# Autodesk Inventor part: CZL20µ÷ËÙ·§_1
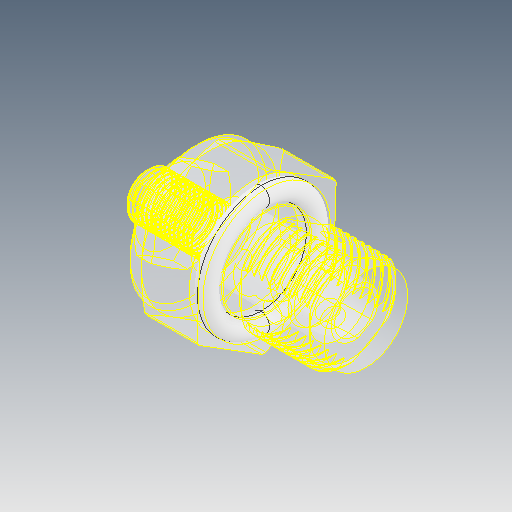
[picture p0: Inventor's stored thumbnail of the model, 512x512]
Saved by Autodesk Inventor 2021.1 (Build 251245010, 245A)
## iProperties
Created: 2021-05
Part Number: CZL20µ÷ËÙ·§_1
Material: Ogólny
Document SubType Name: Modeling
Designer: user
Density: 1 g/cm^3
Appearance: Domyślna
Author: user
Revision Number: ÈÎºÎ
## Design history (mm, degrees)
feature "NONE"
feature "Złożony1"
node "Bryła1"
body "Srf1"
